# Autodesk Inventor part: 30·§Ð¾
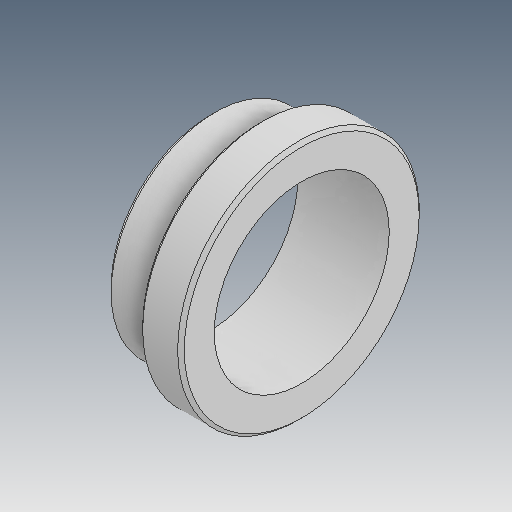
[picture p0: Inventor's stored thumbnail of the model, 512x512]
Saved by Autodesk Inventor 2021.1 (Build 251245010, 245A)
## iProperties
Created: 2019-12
Part Number: 30·§Ð¾
Material: Ogólny
Document SubType Name: Modeling
Designer: user
Density: 1 g/cm^3
Appearance: Domyślna
Author: user
Revision Number: ÈÎºÎ
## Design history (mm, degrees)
feature "ÊäÈë1"
node "Bryła1"
